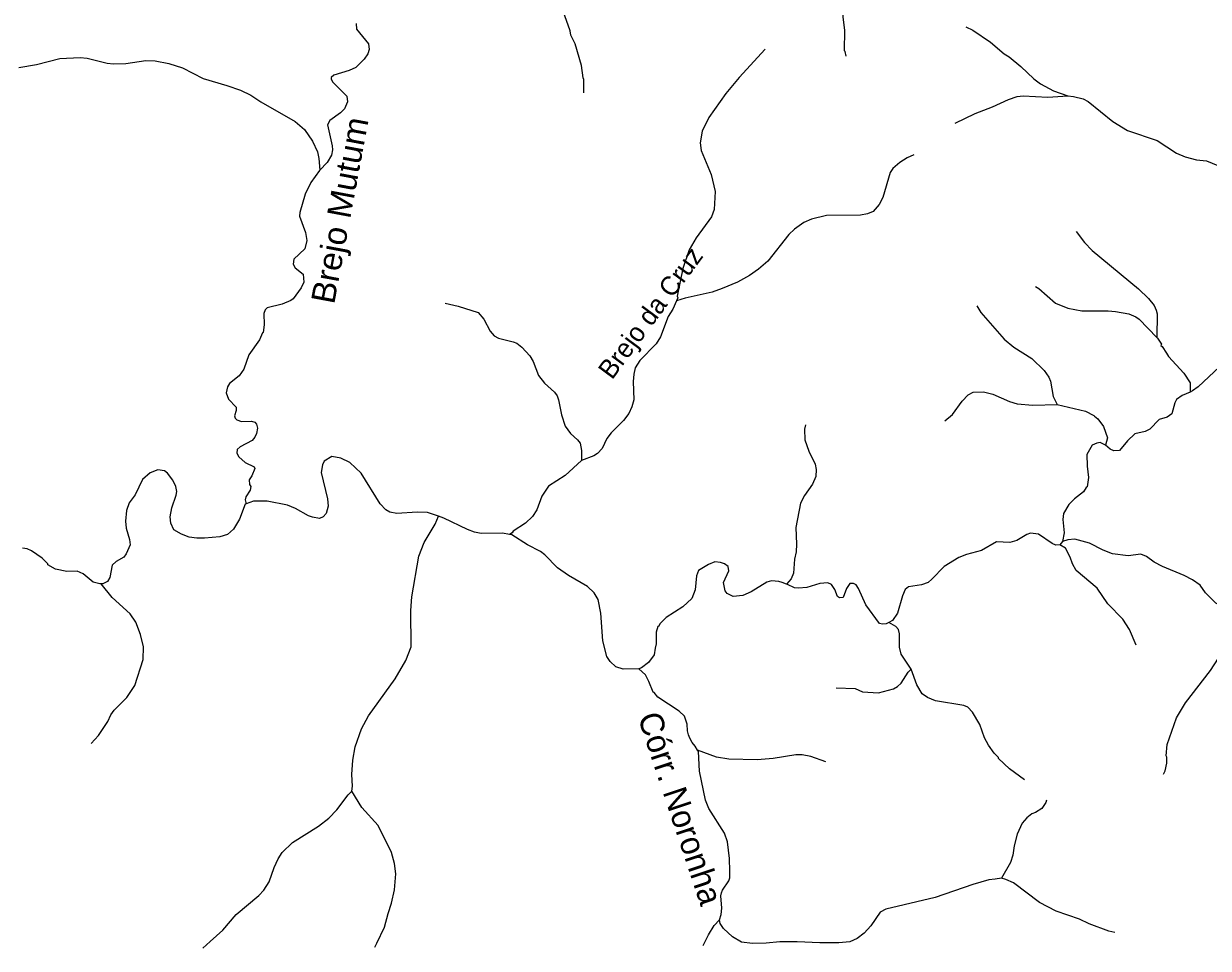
# Model space of a CAD drawing. Extents: x 280.4 to 335.6, y 8893.9 to 8949.5.
# Drawn here: x 294.07 to 304.07, y 8894.01 to 8901.81 of the extents above; entities that cross this region are included whole.
import ezdxf
from ezdxf.enums import TextEntityAlignment as Align

# ---------------------------------------------------------------- set-up
doc = ezdxf.new("R2010")
doc.units = 0
doc.header["$LTSCALE"] = 0.064
doc.layers.add('61', color=7, linetype='Continuous')
doc.layers.add('7', color=7, linetype='Continuous', lineweight=25)

msp = doc.modelspace()

# ---------------------------------------------------------------- linework, layer by layer
at = {"layer": '7'}
msp.add_line((302.841, 8897.4394), (302.8201, 8897.4113), dxfattribs=at)
for points in [[(301.0142, 8901.5392), (301.0074, 8901.5778), (301.001, 8901.5839), (301.004, 8901.7568), (300.9881, 8901.868), (300.9866, 8901.9374), (301.0012, 8902.02), (301.0114, 8902.0464), (301.0309, 8902.0705), (301.1211, 8902.2348), (301.14, 8902.3044), (301.1558, 8902.4383), (301.148, 8902.5262), (301.1336, 8902.583), (301.0977, 8902.6399), (300.9577, 8902.7468), (300.9206, 8902.7911), (300.8972, 8902.8389), (300.8858, 8902.91), (300.8791, 8903.0905), (300.8583, 8903.1801), (300.7928, 8903.281), (300.7802, 8903.3113), (300.7723, 8903.3679)], [(298.7974, 8901.2278), (298.7987, 8901.3417), (298.7925, 8901.3543), (298.7792, 8901.4599), (298.7262, 8901.6422), (298.6884, 8901.7153), (298.6815, 8901.7511), (298.5951, 8901.9974), (298.5486, 8902.0677), (298.5182, 8902.1017)], [(296.8753, 8901.813), (296.8783, 8901.7652), (296.9781, 8901.6406), (296.9848, 8901.5938), (296.9737, 8901.5586), (296.9439, 8901.5127), (296.8731, 8901.4434), (296.8169, 8901.4161), (296.6861, 8901.3782), (296.6636, 8901.3588), (296.6626, 8901.3436), (296.6781, 8901.3187), (296.7958, 8901.1991), (296.8011, 8901.153), (296.7773, 8901.0937), (296.7413, 8901.0591), (296.6538, 8900.995), (296.6337, 8900.9578), (296.6732, 8900.7805), (296.6747, 8900.746), (296.6662, 8900.703), (296.6288, 8900.6412), (296.5671, 8900.5756)], [(302.025, 8901.786), (302.0835, 8901.7568), (302.2344, 8901.6556), (302.3506, 8901.5571), (302.392, 8901.5328), (302.4913, 8901.4513), (302.6011, 8901.3467), (302.657, 8901.3031), (302.7674, 8901.2438), (302.886, 8901.2024)], [(300.3308, 8901.5973), (300.1096, 8901.358), (299.9967, 8901.2225), (299.8539, 8901.0189), (299.7983, 8900.9042), (299.7807, 8900.8053), (299.7901, 8900.7404), (299.8751, 8900.5374), (299.9082, 8900.3958), (299.8987, 8900.2432), (299.8765, 8900.18), (299.7483, 8900.0051), (299.6888, 8899.9032), (299.6337, 8899.7456), (299.5858, 8899.5104), (299.5926, 8899.4972), (299.581, 8899.4716)], [(294.0265, 8901.4433), (294.1731, 8901.4679), (294.3718, 8901.5169), (294.5439, 8901.5265), (294.6014, 8901.5202), (294.7722, 8901.4791), (294.8258, 8901.4724), (294.9282, 8901.4763), (295.0981, 8901.5026), (295.1772, 8901.4978), (295.2923, 8901.4755), (295.4089, 8901.4382), (295.5816, 8901.3503), (295.7831, 8901.2912), (295.8982, 8901.2495), (295.9839, 8901.2082), (296.0697, 8901.1527), (296.3587, 8900.9871), (296.4392, 8900.9178), (296.5072, 8900.819), (296.5478, 8900.7289), (296.5596, 8900.675), (296.5671, 8900.5756)], [(301.9343, 8900.9733), (302.1053, 8901.0544), (302.2498, 8901.1091), (302.3853, 8901.1728), (302.4591, 8901.1973), (302.51, 8901.2035), (302.7184, 8901.1923), (302.886, 8901.2024)], [(302.886, 8901.2024), (302.9351, 8901.1984), (303.0167, 8901.1764), (303.0597, 8901.1549), (303.2685, 8900.9864), (303.391, 8900.9112), (303.6412, 8900.8244), (303.8059, 8900.7198), (303.8776, 8900.6871), (303.9731, 8900.6631), (304.0577, 8900.6531), (304.1533, 8900.6141), (304.1934, 8900.5495)], [(301.5867, 8900.7034), (301.5303, 8900.6803), (301.4668, 8900.6409), (301.4094, 8900.5897), (301.3867, 8900.5547), (301.3256, 8900.3437), (301.2945, 8900.2849), (301.2416, 8900.2277), (301.1961, 8900.2073), (301.136, 8900.1943), (300.8472, 8900.1924), (300.7225, 8900.1628), (300.6576, 8900.1338), (300.5776, 8900.0764), (300.5291, 8900.0328), (300.3539, 8899.8082), (300.2734, 8899.7391), (300.1975, 8899.6852), (300.0979, 8899.6301), (299.9678, 8899.5749), (299.8822, 8899.5465), (299.6542, 8899.4942), (299.581, 8899.4716)], [(296.5671, 8900.5756), (296.5652, 8900.5736), (296.4911, 8900.4715), (296.4445, 8900.3737), (296.3998, 8900.2183), (296.3967, 8900.1864), (296.4476, 8900.0498), (296.4588, 8899.9816), (296.4417, 8899.9124), (296.3489, 8899.8235), (296.3438, 8899.7829), (296.3584, 8899.75), (296.4283, 8899.6967), (296.4316, 8899.6306), (296.4106, 8899.5805), (296.3425, 8899.4897), (296.3222, 8899.4744), (296.2489, 8899.4435), (296.122, 8899.4138), (296.1062, 8899.3971), (296.0942, 8899.3659), (296.0989, 8899.2686), (296.0897, 8899.2036), (296.083, 8899.2018), (296.0587, 8899.143), (295.9668, 8899.0162), (295.9263, 8898.8943), (295.8857, 8898.8393), (295.8061, 8898.7753)], [(302.9569, 8900.0588), (303.0287, 8899.9656), (303.0915, 8899.8964), (303.4839, 8899.5743), (303.5687, 8899.4912), (303.6153, 8899.4339), (303.6344, 8899.3938), (303.6411, 8899.3624), (303.6392, 8899.1627)], [(302.6148, 8899.5929), (302.6423, 8899.5759), (302.7825, 8899.4523), (302.8873, 8899.4109), (303.0067, 8899.3872), (303.227, 8899.3883), (303.2909, 8899.3833), (303.403, 8899.3616), (303.462, 8899.3371), (303.4908, 8899.3179), (303.6392, 8899.1627)], [(297.6273, 8899.452), (297.7354, 8899.4285), (297.9045, 8899.3736), (297.9537, 8899.318), (298.0078, 8899.2154), (298.0397, 8899.1767), (298.0774, 8899.1565), (298.201, 8899.1268), (298.2318, 8899.1135), (298.2735, 8899.0816), (298.3417, 8899.0073), (298.3701, 8898.9589), (298.4153, 8898.8423), (298.4663, 8898.7772), (298.5501, 8898.7011), (298.5718, 8898.6695), (298.5849, 8898.6354), (298.6086, 8898.5096), (298.6404, 8898.4144), (298.6856, 8898.3532), (298.7452, 8898.2997), (298.7663, 8898.2704), (298.7793, 8898.2081), (298.7779, 8898.1238)], [(299.581, 8899.4716), (299.5495, 8899.4018), (299.5094, 8899.3398), (299.4454, 8899.1675), (299.4095, 8899.1085), (299.272, 8898.9692), (299.2319, 8898.9062), (299.2199, 8898.8536), (299.2145, 8898.791), (299.2205, 8898.6366), (299.2051, 8898.5781), (299.1795, 8898.5206), (299.134, 8898.4622), (299.0295, 8898.3586), (298.9929, 8898.3089), (298.9525, 8898.2263), (298.9149, 8898.1836), (298.8828, 8898.1646), (298.7779, 8898.1238)], [(302.1171, 8899.4296), (302.152, 8899.373), (302.3485, 8899.1489), (302.4299, 8899.0817), (302.5837, 8898.9858), (302.6885, 8898.884), (302.728, 8898.8265), (302.7418, 8898.7933), (302.7619, 8898.6639), (302.7984, 8898.5972)], [(303.6392, 8899.1627), (303.645, 8899.1566), (303.6777, 8899.1069), (303.674, 8899.0938), (303.6849, 8899.0866), (303.7212, 8899.03), (303.7383, 8899.0035), (303.8682, 8898.8605), (303.9196, 8898.7791), (303.92, 8898.7019)], [(304.434, 8898.8963), (304.3756, 8898.9197), (304.2937, 8898.9405), (304.2425, 8898.9437), (304.1953, 8898.9311), (304.1679, 8898.9138), (303.9892, 8898.7466), (303.9414, 8898.711), (303.92, 8898.7019)], [(295.8061, 8898.7753), (295.7871, 8898.7463), (295.778, 8898.6953), (295.7969, 8898.6421), (295.862, 8898.5757), (295.8624, 8898.5461), (295.8466, 8898.5014), (295.8518, 8898.4804), (295.8682, 8898.4666), (295.9064, 8898.4544), (295.9905, 8898.455), (296.0178, 8898.448), (296.0335, 8898.4295), (296.0413, 8898.3958), (296.0334, 8898.352), (296.0191, 8898.3206), (295.9955, 8898.2925), (295.8963, 8898.2401), (295.8703, 8898.216), (295.8675, 8898.1847), (295.8829, 8898.1554), (295.9385, 8898.1077), (296.012, 8898.0707), (296.0187, 8898.0561), (295.9935, 8897.9938), (295.9715, 8897.9616), (295.9729, 8897.9211), (295.9852, 8897.9047), (295.9784, 8897.8724), (295.9441, 8897.8162), (295.9371, 8897.7917), (295.9456, 8897.7586)], [(301.8487, 8898.4601), (301.9117, 8898.5114), (301.9946, 8898.6242), (302.0442, 8898.6785), (302.0874, 8898.7007), (302.1738, 8898.7026), (302.253, 8898.6845), (302.3955, 8898.6218), (302.46, 8898.6026), (302.5913, 8898.5903), (302.7984, 8898.5972)], [(303.92, 8898.7019), (303.8524, 8898.6733), (303.8053, 8898.6386), (303.7918, 8898.6116), (303.7653, 8898.5181), (303.7256, 8898.4903), (303.659, 8898.4692), (303.5797, 8898.3885), (303.5395, 8898.3699), (303.4526, 8898.3486), (303.3906, 8898.29)], [(302.7984, 8898.5972), (303.0373, 8898.5418), (303.107, 8898.5039), (303.1134, 8898.4987), (303.1406, 8898.4767), (303.1882, 8898.4118), (303.2219, 8898.3152), (303.2043, 8898.2538)], [(300.6716, 8898.4265), (300.6621, 8898.3895), (300.6653, 8898.2994), (300.6986, 8898.2033), (300.7531, 8898.0918), (300.7609, 8898.049), (300.7578, 8897.9904), (300.7289, 8897.9233), (300.6631, 8897.83), (300.628, 8897.7627), (300.628, 8897.7626), (300.5899, 8897.5578), (300.5961, 8897.4182), (300.5912, 8897.3542), (300.5776, 8897.2924), (300.5738, 8897.2129), (300.5706, 8897.1739), (300.5498, 8897.1254), (300.5097, 8897.0791)], [(303.2043, 8898.2538), (303.1598, 8898.2748), (303.1321, 8898.2718), (303.0934, 8898.2546), (303.0479, 8898.1743), (303.0495, 8898.0761), (303.0605, 8897.9801), (303.0496, 8897.9008), (303.0414, 8897.897), (303.0204, 8897.8583), (302.9434, 8897.7997), (302.8963, 8897.7528), (302.8513, 8897.6769), (302.8463, 8897.6269), (302.8558, 8897.5131), (302.841, 8897.4394)], [(303.3906, 8898.29), (303.3228, 8898.2099), (303.2755, 8898.2055), (303.2446, 8898.2194), (303.2043, 8898.2538)], [(297.5699, 8897.6538), (297.4776, 8897.6848), (297.3896, 8897.6866), (297.2178, 8897.6756), (297.1596, 8897.6889), (297.1254, 8897.7064), (297.0779, 8897.7571), (296.9183, 8898.0159), (296.8203, 8898.1073), (296.7468, 8898.1449), (296.6683, 8898.1577), (296.6045, 8898.1176), (296.5917, 8898.0881), (296.5806, 8898.0226), (296.6333, 8897.7995), (296.6379, 8897.7391), (296.621, 8897.6771), (296.5959, 8897.6472), (296.5655, 8897.634), (296.5058, 8897.6444), (296.4718, 8897.6573), (296.3636, 8897.7199), (296.2942, 8897.7474), (296.123, 8897.7809), (296.0071, 8897.7811), (295.9456, 8897.7586)], [(295.9456, 8897.7586), (295.9379, 8897.7558), (295.8904, 8897.6293), (295.8388, 8897.5432), (295.7869, 8897.4997), (295.7232, 8897.4806), (295.593, 8897.4676), (295.529, 8897.4676), (295.465, 8897.4774), (295.3992, 8897.5024), (295.3349, 8897.5401), (295.31, 8897.5963), (295.3029, 8897.649), (295.3177, 8897.725), (295.3556, 8897.8307), (295.3585, 8897.861), (295.3509, 8897.906), (295.3249, 8897.9569), (295.2802, 8898.0161), (295.2567, 8898.0356), (295.1996, 8898.0462), (295.1357, 8898.0189), (295.0689, 8897.9641), (295.0082, 8897.8355), (294.9581, 8897.7681), (294.9335, 8897.7017), (294.9253, 8897.6131), (294.9317, 8897.554), (294.9605, 8897.4573), (294.9666, 8897.4118), (294.9329, 8897.3358), (294.9128, 8897.3069), (294.847, 8897.2714), (294.8124, 8897.2416), (294.7925, 8897.1357), (294.774, 8897.1027), (294.735, 8897.0816), (294.7215, 8897.0815)], [(298.7779, 8898.1238), (298.6409, 8897.9986), (298.5007, 8897.9067), (298.4433, 8897.822), (298.4007, 8897.7081), (298.3652, 8897.6516), (298.3055, 8897.5951), (298.2022, 8897.5281), (298.1937, 8897.5137), (298.1714, 8897.4988)], [(296.8392, 8895.3317), (296.8443, 8895.3757), (296.838, 8895.4742), (296.848, 8895.5931), (296.8671, 8895.706), (296.9193, 8895.858), (296.9801, 8895.9689), (297.2037, 8896.2803), (297.2941, 8896.4351), (297.3384, 8896.5496), (297.3355, 8896.8584), (297.3449, 8896.9718), (297.4041, 8897.3172), (297.4501, 8897.4317), (297.5416, 8897.586), (297.5699, 8897.6538)], [(298.1714, 8897.4988), (298.1107, 8897.5109), (297.9319, 8897.5092), (297.8742, 8897.5188), (297.8166, 8897.5403), (297.6168, 8897.638), (297.5699, 8897.6538)], [(298.8854, 8897.0064), (298.8296, 8897.0592), (298.6693, 8897.1535), (298.5755, 8897.2185), (298.4701, 8897.3289), (298.4331, 8897.3567), (298.3212, 8897.4118), (298.1891, 8897.4953), (298.1714, 8897.4988)], [(302.8201, 8897.4113), (302.7864, 8897.4093), (302.7548, 8897.4234), (302.6384, 8897.5025), (302.5723, 8897.5106), (302.5409, 8897.4995), (302.4567, 8897.4473), (302.3962, 8897.4309), (302.2851, 8897.437), (302.1586, 8897.3643), (302.032, 8897.3309), (301.9651, 8897.306), (301.8421, 8897.2293), (301.7393, 8897.1218), (301.706, 8897.095), (301.6514, 8897.0748), (301.541, 8897.0568), (301.5132, 8897.0359), (301.4895, 8896.9812), (301.4484, 8896.8343), (301.4048, 8896.7728), (301.3761, 8896.7553)], [(304.3263, 8896.8448), (304.2218, 8896.8781), (304.138, 8896.9206), (304.0512, 8897.0065), (304.0065, 8897.0715), (303.9412, 8897.1161), (303.8705, 8897.1538), (303.6859, 8897.2285), (303.6156, 8897.2667), (303.5516, 8897.3139), (303.5041, 8897.333), (303.3965, 8897.3205), (303.2635, 8897.3375), (303.1846, 8897.366), (303.0695, 8897.4263), (302.9455, 8897.4593), (302.8879, 8897.4551), (302.841, 8897.4394)], [(294.7215, 8897.0815), (294.709, 8897.0815), (294.654, 8897.0978), (294.5676, 8897.168), (294.5182, 8897.1892), (294.4319, 8897.1879), (294.3352, 8897.206), (294.2703, 8897.2438), (294.2688, 8897.2521), (294.2228, 8897.2999), (294.132, 8897.3619), (294.0943, 8897.3777), (294.0566, 8897.3844)], [(303.4637, 8896.5646), (303.4084, 8896.6986), (303.3513, 8896.7853), (303.2253, 8896.914), (303.1358, 8897.047), (302.9588, 8897.1953), (302.9258, 8897.2509), (302.9071, 8897.3093), (302.8679, 8897.3832), (302.8201, 8897.4113)], [(300.5097, 8897.0791), (300.4751, 8897.0944), (300.4465, 8897.1028), (300.3849, 8897.1076), (300.3439, 8897.0982), (300.2116, 8897.0147), (300.142, 8896.9831), (300.061, 8896.9751), (300.0086, 8897.0019), (299.9918, 8897.025), (299.9792, 8897.0947), (300.0231, 8897.193), (300.0171, 8897.2285), (299.9868, 8897.2519), (299.9535, 8897.2634), (299.9063, 8897.269), (299.8516, 8897.2456), (299.7667, 8897.1956), (299.7489, 8897.1503), (299.7385, 8897.031), (299.7105, 8896.958), (299.636, 8896.8882), (299.4946, 8896.798), (299.4405, 8896.7453), (299.4321, 8896.7264), (299.4243, 8896.7235), (299.4097, 8896.6736), (299.4095, 8896.5753), (299.4001, 8896.5392), (299.3928, 8896.4831), (299.3458, 8896.4177), (299.2861, 8896.374), (299.264, 8896.3659)], [(294.6367, 8895.7348), (294.6991, 8895.8033), (294.7781, 8895.9196), (294.8024, 8895.9774), (294.8293, 8896.0154), (294.938, 8896.1227), (295.0047, 8896.2247), (295.0753, 8896.4433), (295.0786, 8896.5504), (295.0531, 8896.6551), (295.0138, 8896.7591), (294.9657, 8896.8305), (294.8149, 8896.9671), (294.7215, 8897.0815)], [(301.3761, 8896.7553), (301.3513, 8896.746), (301.3214, 8896.742), (301.2949, 8896.7486), (301.1812, 8896.9053), (301.1184, 8897.0438), (301.099, 8897.0748), (301.0751, 8897.0852), (301.0458, 8897.0851), (301.018, 8897.0443), (300.9886, 8896.9671), (300.9574, 8896.9645), (300.941, 8896.9763), (300.9191, 8897.0358), (300.8909, 8897.076), (300.8591, 8897.0914), (300.7911, 8897.0859), (300.6818, 8897.0532), (300.6122, 8897.0454), (300.5771, 8897.0503), (300.5186, 8897.0767), (300.5097, 8897.0791)], [(299.264, 8896.3659), (299.1298, 8896.362), (299.0674, 8896.3834), (299.0194, 8896.4265), (298.9921, 8896.4704), (298.9589, 8896.6025), (298.9424, 8896.8358), (298.92, 8896.9494), (298.8854, 8897.0064)], [(303.6948, 8895.4756), (303.7083, 8895.503), (303.7227, 8895.5683), (303.7243, 8895.6193), (303.7179, 8895.6318), (303.7263, 8895.7251), (303.8041, 8895.9515), (303.8811, 8896.0778), (304.0937, 8896.3513), (304.2266, 8896.5592), (304.2725, 8896.6193), (304.3286, 8896.7371), (304.3319, 8896.7934), (304.3263, 8896.8448)], [(301.5634, 8896.3617), (301.4803, 8896.4895), (301.4662, 8896.5472), (301.4662, 8896.6608), (301.4566, 8896.6977), (301.434, 8896.7224), (301.3761, 8896.7553)], [(299.7596, 8895.6796), (299.7396, 8895.7109), (299.7138, 8895.7428), (299.6933, 8895.7803), (299.6821, 8895.8092), (299.6743, 8895.8413), (299.6715, 8895.8987), (299.6495, 8895.9652), (299.6032, 8896.0084), (299.4224, 8896.1259), (299.3921, 8896.1652), (299.3828, 8896.1694), (299.3484, 8896.2592), (299.3192, 8896.3147), (299.264, 8896.3659)], [(300.9301, 8896.2034), (301.0906, 8896.1995), (301.1534, 8896.1717), (301.2864, 8896.1627), (301.4137, 8896.1957), (301.4483, 8896.2154), (301.4802, 8896.2454), (301.5382, 8896.3384), (301.5634, 8896.3617)], [(302.5217, 8895.4288), (302.3938, 8895.5197), (302.3022, 8895.6068), (302.3004, 8895.6159), (302.2638, 8895.6546), (302.2175, 8895.7202), (302.1831, 8895.783), (302.1432, 8895.8958), (302.0831, 8895.9984), (302.0419, 8896.0409), (302.0099, 8896.0569), (301.7693, 8896.0957), (301.7021, 8896.1224), (301.6569, 8896.1533), (301.6111, 8896.2313), (301.5634, 8896.3617)], [(299.9444, 8894.2466), (299.9581, 8894.2912), (299.9628, 8894.3456), (299.9566, 8894.4474), (299.96, 8894.4739), (299.9686, 8894.4976), (300.022, 8894.5754), (300.0331, 8894.6009), (300.0317, 8894.6927), (300.0281, 8894.7283), (300.0299, 8894.7648), (300.0109, 8894.9048), (299.986, 8894.9775), (299.8534, 8895.1855), (299.8256, 8895.2567), (299.7744, 8895.502), (299.766, 8895.6683), (299.7596, 8895.6796)], [(300.8418, 8895.5787), (300.7171, 8895.6238), (300.6434, 8895.638), (300.5905, 8895.638), (300.399, 8895.6081), (300.2624, 8895.5969), (300.0229, 8895.6014), (299.9198, 8895.6193), (299.7596, 8895.6796)], [(295.5782, 8894.0058), (295.6409, 8894.062), (295.7484, 8894.1583), (295.8619, 8894.2909), (296.0518, 8894.452), (296.0951, 8894.4973), (296.1403, 8894.5675), (296.1823, 8894.688), (296.2167, 8894.7619), (296.2511, 8894.8144), (296.336, 8894.8988), (296.5568, 8895.038), (296.6444, 8895.1055), (296.7104, 8895.1759), (296.806, 8895.3022), (296.8392, 8895.3317)], [(297.0324, 8894.014), (297.0499, 8894.0497), (297.1154, 8894.1835), (297.1439, 8894.2993), (297.1739, 8894.3881), (297.1991, 8894.4987), (297.2105, 8894.6337), (297.1997, 8894.7208), (297.1734, 8894.8134), (297.0598, 8895.0437), (296.9216, 8895.195), (296.8392, 8895.3317)], [(302.7056, 8895.2567), (302.7002, 8895.2371), (302.6677, 8895.1862), (302.6151, 8895.1522), (302.582, 8895.1416), (302.5406, 8895.1086), (302.5007, 8895.0616), (302.4602, 8894.9703), (302.4326, 8894.8707), (302.4223, 8894.793), (302.4026, 8894.7288), (302.3264, 8894.5972)], [(302.3264, 8894.5972), (302.2743, 8894.5895), (302.2211, 8894.584), (302.0835, 8894.5457), (301.7652, 8894.4358), (301.3486, 8894.3348), (301.3006, 8894.311), (301.2231, 8894.1956), (301.1671, 8894.1348), (301.1073, 8894.0896), (301.0465, 8894.0595), (300.9529, 8894.0516), (300.7913, 8894.0516), (300.6011, 8894.0611), (300.4555, 8894.0611), (300.3396, 8894.0483), (300.2225, 8894.0454), (300.1294, 8894.0574), (300.0551, 8894.1016), (299.9785, 8894.1739), (299.9509, 8894.215), (299.9444, 8894.2466)], [(303.2833, 8894.1384), (303.2349, 8894.1494), (303.0661, 8894.2114), (302.9871, 8894.2514), (302.7881, 8894.3197), (302.6484, 8894.3919), (302.4278, 8894.5592), (302.364, 8894.5876), (302.3264, 8894.5972)], [(299.8065, 8894.0294), (299.8504, 8894.1187), (299.899, 8894.1969), (299.9444, 8894.2466)]]:
    msp.add_lwpolyline(points, dxfattribs=at)

# ---------------------------------------------------------------- texts
at = {"layer": '61', "width": 1.05}
msp.add_text('Brejo Mutum', height=0.2, rotation=79.426, dxfattribs=at).set_placement((296.8348, 8900.2189), align=Align.CENTER)
at = {"layer": '61'}
for s, height, rotation, p in [('Brejo da Cruz', 0.16, 53.531, (299.4254, 8899.3252)), ('Córr. Noronha', 0.2, 288.435, (299.5196, 8895.1563))]:
    msp.add_text(s, height=height, rotation=rotation, dxfattribs=at).set_placement(p, align=Align.CENTER)

doc.saveas('drawing.dxf')
